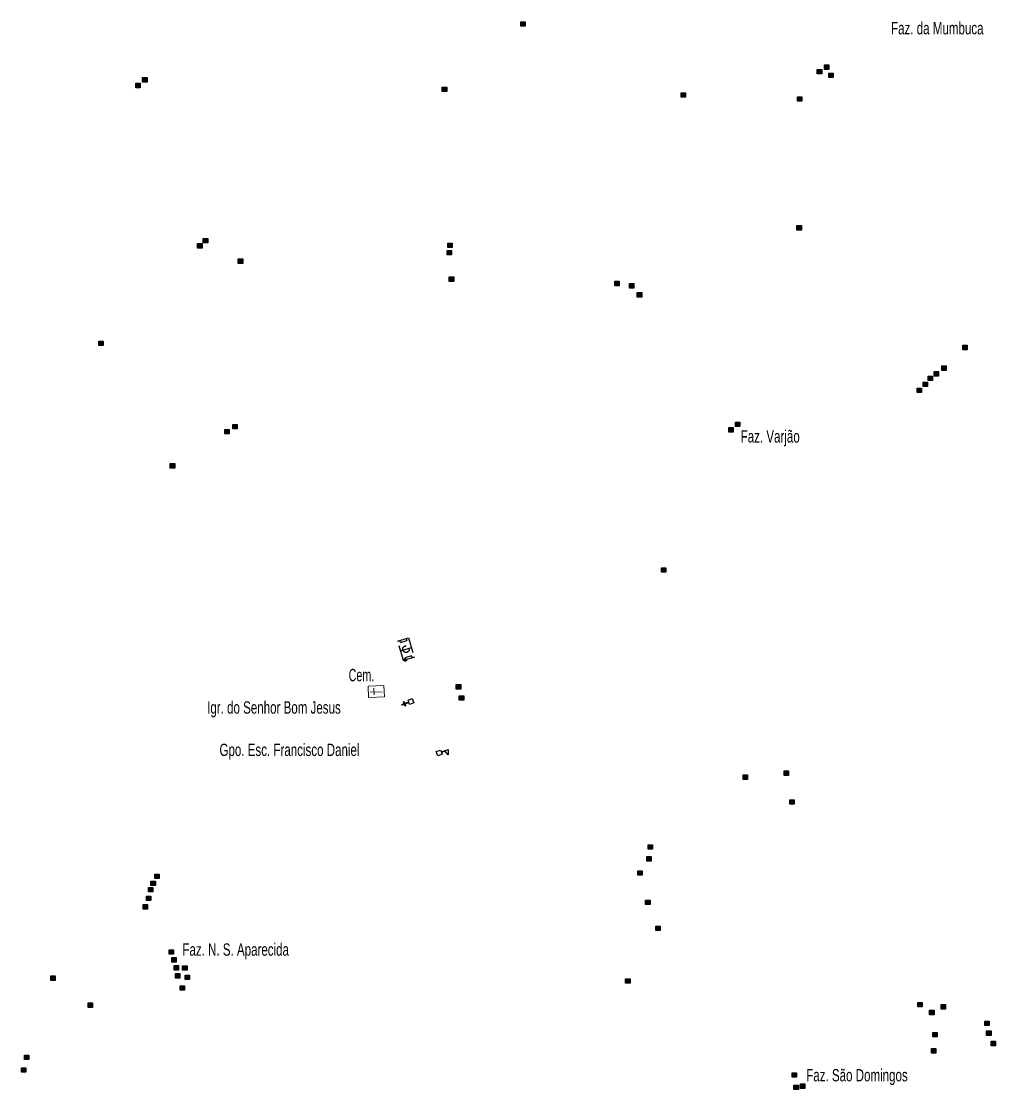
# Model space of a CAD drawing. Extents: x 265.7 to 292.1, y 7676.2 to 7704.2.
# Drawn here: x 273.12 to 279.43, y 7683.25 to 7690.17 of the extents above; entities that cross this region are included whole.
import ezdxf

# ---------------------------------------------------------------- set-up
doc = ezdxf.new("R2010")
doc.units = 0
doc.header["$LTSCALE"] = 0.032
doc.header["$PDMODE"] = 32
doc.header["$PDSIZE"] = 0.016
doc.linetypes.add('MEDIUM_DASHED', pattern=[4.5, 3, -1.5])
for name, color, linetype, lineweight in [('14', 7, 'MEDIUM_DASHED', 25), ('2', 7, 'Continuous', 25), ('21', 7, 'MEDIUM_DASHED', 13), ('4', 7, 'Continuous', 25), ('6', 7, 'Continuous', 25)]:
    doc.layers.add(name, color=color, linetype=linetype, lineweight=lineweight)
doc.layers.add('61', color=7, linetype='Continuous')

msp = doc.modelspace()

# ---------------------------------------------------------------- hatches: boundary and pattern name
at = {"layer": '2'}
for points in [[(276.3557, 7690.1714), (276.3847, 7690.1714), (276.3847, 7690.1424), (276.3557, 7690.1424)], [(278.3241, 7689.8922), (278.3531, 7689.8922), (278.3531, 7689.8632), (278.3241, 7689.8632)], [(273.9054, 7689.8099), (273.9344, 7689.8099), (273.9344, 7689.7809), (273.9054, 7689.7809)], [(278.2773, 7689.8631), (278.3063, 7689.8631), (278.3063, 7689.8341), (278.2773, 7689.8341)], [(278.3516, 7689.839), (278.3806, 7689.839), (278.3806, 7689.81), (278.3516, 7689.81)], [(273.8602, 7689.7727), (273.8892, 7689.7727), (273.8892, 7689.7437), (273.8602, 7689.7437)], [(275.8472, 7689.7485), (275.8762, 7689.7485), (275.8762, 7689.7195), (275.8472, 7689.7195)], [(277.3952, 7689.7114), (277.4242, 7689.7114), (277.4242, 7689.6824), (277.3952, 7689.6824)], [(278.149, 7689.6856), (278.178, 7689.6856), (278.178, 7689.6566), (278.149, 7689.6566)], [(278.145, 7688.8503), (278.174, 7688.8503), (278.174, 7688.8213), (278.145, 7688.8213)], [(274.2614, 7688.7333), (274.2904, 7688.7333), (274.2904, 7688.7043), (274.2614, 7688.7043)], [(274.2977, 7688.7672), (274.3267, 7688.7672), (274.3267, 7688.7382), (274.2977, 7688.7382)], [(275.8828, 7688.7373), (275.9118, 7688.7373), (275.9118, 7688.7083), (275.8828, 7688.7083)], [(274.5253, 7688.634), (274.5543, 7688.634), (274.5543, 7688.605), (274.5253, 7688.605)], [(275.8779, 7688.6888), (275.9069, 7688.6888), (275.9069, 7688.6598), (275.8779, 7688.6598)], [(275.8924, 7688.5178), (275.9214, 7688.5178), (275.9214, 7688.4888), (275.8924, 7688.4888)], [(276.965, 7688.4895), (276.994, 7688.4895), (276.994, 7688.4605), (276.965, 7688.4605)], [(277.0601, 7688.4742), (277.0891, 7688.4742), (277.0891, 7688.4452), (277.0601, 7688.4452)], [(277.1103, 7688.4154), (277.1393, 7688.4154), (277.1393, 7688.3864), (277.1103, 7688.3864)], [(273.6207, 7688.1012), (273.6497, 7688.1012), (273.6497, 7688.0722), (273.6207, 7688.0722)], [(279.2199, 7688.0747), (279.2489, 7688.0747), (279.2489, 7688.0457), (279.2199, 7688.0457)], [(279.0835, 7687.9408), (279.1125, 7687.9408), (279.1125, 7687.9118), (279.0835, 7687.9118)], [(278.9956, 7687.8746), (279.0246, 7687.8746), (279.0246, 7687.8456), (278.9956, 7687.8456)], [(279.0343, 7687.9036), (279.0633, 7687.9036), (279.0633, 7687.8746), (279.0343, 7687.8746)], [(278.9632, 7687.8358), (278.9922, 7687.8358), (278.9922, 7687.8068), (278.9632, 7687.8068)], [(278.9246, 7687.7971), (278.9536, 7687.7971), (278.9536, 7687.7681), (278.9246, 7687.7681)], [(274.4372, 7687.5291), (274.4662, 7687.5291), (274.4662, 7687.5001), (274.4372, 7687.5001)], [(274.4898, 7687.5607), (274.5188, 7687.5607), (274.5188, 7687.5317), (274.4898, 7687.5317)], [(277.7035, 7687.5405), (277.7325, 7687.5405), (277.7325, 7687.5115), (277.7035, 7687.5115)], [(277.7471, 7687.5759), (277.7761, 7687.5759), (277.7761, 7687.5469), (277.7471, 7687.5469)], [(274.0846, 7687.3072), (274.1136, 7687.3072), (274.1136, 7687.2782), (274.0846, 7687.2782)], [(277.2676, 7686.6317), (277.2966, 7686.6317), (277.2966, 7686.6027), (277.2676, 7686.6027)], [(275.9376, 7685.8746), (275.9666, 7685.8746), (275.9666, 7685.8456), (275.9376, 7685.8456)], [(275.9571, 7685.8021), (275.9861, 7685.8021), (275.9861, 7685.7731), (275.9571, 7685.7731)], [(278.0626, 7685.3146), (278.0916, 7685.3146), (278.0916, 7685.2856), (278.0626, 7685.2856)], [(277.7962, 7685.2887), (277.8252, 7685.2887), (277.8252, 7685.2597), (277.7962, 7685.2597)], [(278.099, 7685.1274), (278.128, 7685.1274), (278.128, 7685.0984), (278.099, 7685.0984)], [(277.1805, 7684.8361), (277.2095, 7684.8361), (277.2095, 7684.8071), (277.1805, 7684.8071)], [(277.1725, 7684.7594), (277.2015, 7684.7594), (277.2015, 7684.7304), (277.1725, 7684.7304)], [(273.9832, 7684.6464), (274.0122, 7684.6464), (274.0122, 7684.6174), (273.9832, 7684.6174)], [(277.1143, 7684.6673), (277.1433, 7684.6673), (277.1433, 7684.6383), (277.1143, 7684.6383)], [(273.9433, 7684.5592), (273.9723, 7684.5592), (273.9723, 7684.5302), (273.9433, 7684.5302)], [(273.9587, 7684.6004), (273.9877, 7684.6004), (273.9877, 7684.5714), (273.9587, 7684.5714)], [(273.9296, 7684.5028), (273.9586, 7684.5028), (273.9586, 7684.4738), (273.9296, 7684.4738)], [(277.1643, 7684.4769), (277.1933, 7684.4769), (277.1933, 7684.4479), (277.1643, 7684.4479)], [(273.9087, 7684.4485), (273.9377, 7684.4485), (273.9377, 7684.4195), (273.9087, 7684.4195)], [(277.2306, 7684.309), (277.2596, 7684.309), (277.2596, 7684.28), (277.2306, 7684.28)], [(274.0766, 7684.1557), (274.1056, 7684.1557), (274.1056, 7684.1267), (274.0766, 7684.1267)], [(274.0943, 7684.1049), (274.1233, 7684.1049), (274.1233, 7684.0759), (274.0943, 7684.0759)], [(274.1089, 7684.0524), (274.1379, 7684.0524), (274.1379, 7684.0234), (274.1089, 7684.0234)], [(274.1178, 7684.0007), (274.1468, 7684.0007), (274.1468, 7683.9717), (274.1178, 7683.9717)], [(274.1641, 7684.0511), (274.1931, 7684.0511), (274.1931, 7684.0221), (274.1641, 7684.0221)], [(274.1807, 7683.991), (274.2097, 7683.991), (274.2097, 7683.962), (274.1807, 7683.962)], [(273.3099, 7683.9854), (273.3389, 7683.9854), (273.3389, 7683.9564), (273.3099, 7683.9564)], [(274.1476, 7683.9216), (274.1766, 7683.9216), (274.1766, 7683.8926), (274.1476, 7683.8926)], [(277.0352, 7683.9668), (277.0642, 7683.9668), (277.0642, 7683.9378), (277.0352, 7683.9378)], [(273.5512, 7683.8103), (273.5802, 7683.8103), (273.5802, 7683.7813), (273.5512, 7683.7813)], [(278.9279, 7683.8135), (278.9569, 7683.8135), (278.9569, 7683.7845), (278.9279, 7683.7845)], [(279.0794, 7683.7998), (279.1084, 7683.7998), (279.1084, 7683.7708), (279.0794, 7683.7708)], [(279.0053, 7683.7635), (279.0343, 7683.7635), (279.0343, 7683.7345), (279.0053, 7683.7345)], [(279.3627, 7683.6925), (279.3917, 7683.6925), (279.3917, 7683.6635), (279.3627, 7683.6635)], [(279.0255, 7683.6198), (279.0545, 7683.6198), (279.0545, 7683.5908), (279.0255, 7683.5908)], [(279.3748, 7683.6295), (279.4038, 7683.6295), (279.4038, 7683.6005), (279.3748, 7683.6005)], [(279.0173, 7683.5149), (279.0463, 7683.5149), (279.0463, 7683.4859), (279.0173, 7683.4859)], [(279.404, 7683.5617), (279.433, 7683.5617), (279.433, 7683.5327), (279.404, 7683.5327)], [(273.1388, 7683.473), (273.1678, 7683.473), (273.1678, 7683.444), (273.1388, 7683.444)], [(273.1194, 7683.3906), (273.1484, 7683.3906), (273.1484, 7683.3616), (273.1194, 7683.3616)], [(278.1143, 7683.3584), (278.1433, 7683.3584), (278.1433, 7683.3294), (278.1143, 7683.3294)], [(278.1256, 7683.2775), (278.1546, 7683.2775), (278.1546, 7683.2485), (278.1256, 7683.2485)], [(278.1681, 7683.2857), (278.1971, 7683.2857), (278.1971, 7683.2567), (278.1681, 7683.2567)]]:
    msp.add_hatch(color=256, dxfattribs=at).paths.add_polyline_path(points)

# ---------------------------------------------------------------- linework, layer by layer
at = {"layer": '14'}
for p, q in [((275.5756, 7686.1468), (275.5715, 7686.1605)), ((275.5756, 7686.1468), (275.6182, 7686.1598)), ((275.614, 7686.1735), (275.6182, 7686.1598)), ((275.577, 7686.0936), (275.6469, 7686.115)), ((275.6482, 7686.0618), (275.6057, 7686.0487)), ((275.6099, 7686.0351), (275.6057, 7686.0487)), ((275.6063, 7686.0338), (275.6064, 7686.0339)), ((275.6482, 7686.0618), (275.6523, 7686.0481)), ((275.6506, 7686.0476), (275.651, 7686.0473))]:
    msp.add_line(p, q, dxfattribs=at)
msp.add_lwpolyline([(275.666, 7686.0523), (275.5962, 7686.0309), (275.5578, 7686.1563), (275.6277, 7686.1777)], close=True, dxfattribs=at)
msp.add_circle((275.6119, 7686.1043), 0.0212, dxfattribs=at)
msp.add_point((275.6066, 7686.0341), dxfattribs=at)
at = {"layer": '2'}
for points in [[(276.3557, 7690.1714), (276.3847, 7690.1714), (276.3847, 7690.1424), (276.3557, 7690.1424)], [(278.3241, 7689.8922), (278.3531, 7689.8922), (278.3531, 7689.8632), (278.3241, 7689.8632)], [(273.9054, 7689.8099), (273.9344, 7689.8099), (273.9344, 7689.7809), (273.9054, 7689.7809)], [(278.2773, 7689.8631), (278.3063, 7689.8631), (278.3063, 7689.8341), (278.2773, 7689.8341)], [(278.3516, 7689.839), (278.3806, 7689.839), (278.3806, 7689.81), (278.3516, 7689.81)], [(273.8602, 7689.7727), (273.8892, 7689.7727), (273.8892, 7689.7437), (273.8602, 7689.7437)], [(275.8472, 7689.7485), (275.8762, 7689.7485), (275.8762, 7689.7195), (275.8472, 7689.7195)], [(277.3952, 7689.7114), (277.4242, 7689.7114), (277.4242, 7689.6824), (277.3952, 7689.6824)], [(278.149, 7689.6856), (278.178, 7689.6856), (278.178, 7689.6566), (278.149, 7689.6566)], [(278.145, 7688.8503), (278.174, 7688.8503), (278.174, 7688.8213), (278.145, 7688.8213)], [(274.2614, 7688.7333), (274.2904, 7688.7333), (274.2904, 7688.7043), (274.2614, 7688.7043)], [(274.2977, 7688.7672), (274.3267, 7688.7672), (274.3267, 7688.7382), (274.2977, 7688.7382)], [(275.8828, 7688.7373), (275.9118, 7688.7373), (275.9118, 7688.7083), (275.8828, 7688.7083)], [(274.5253, 7688.634), (274.5543, 7688.634), (274.5543, 7688.605), (274.5253, 7688.605)], [(275.8779, 7688.6888), (275.9069, 7688.6888), (275.9069, 7688.6598), (275.8779, 7688.6598)], [(275.8924, 7688.5178), (275.9214, 7688.5178), (275.9214, 7688.4888), (275.8924, 7688.4888)], [(276.965, 7688.4895), (276.994, 7688.4895), (276.994, 7688.4605), (276.965, 7688.4605)], [(277.0601, 7688.4742), (277.0891, 7688.4742), (277.0891, 7688.4452), (277.0601, 7688.4452)], [(277.1103, 7688.4154), (277.1393, 7688.4154), (277.1393, 7688.3864), (277.1103, 7688.3864)], [(273.6207, 7688.1012), (273.6497, 7688.1012), (273.6497, 7688.0722), (273.6207, 7688.0722)], [(279.2199, 7688.0747), (279.2489, 7688.0747), (279.2489, 7688.0457), (279.2199, 7688.0457)], [(279.0835, 7687.9408), (279.1125, 7687.9408), (279.1125, 7687.9118), (279.0835, 7687.9118)], [(278.9956, 7687.8746), (279.0246, 7687.8746), (279.0246, 7687.8456), (278.9956, 7687.8456)], [(279.0343, 7687.9036), (279.0633, 7687.9036), (279.0633, 7687.8746), (279.0343, 7687.8746)], [(278.9632, 7687.8358), (278.9922, 7687.8358), (278.9922, 7687.8068), (278.9632, 7687.8068)], [(278.9246, 7687.7971), (278.9536, 7687.7971), (278.9536, 7687.7681), (278.9246, 7687.7681)], [(274.4372, 7687.5291), (274.4662, 7687.5291), (274.4662, 7687.5001), (274.4372, 7687.5001)], [(274.4898, 7687.5607), (274.5188, 7687.5607), (274.5188, 7687.5317), (274.4898, 7687.5317)], [(277.7035, 7687.5405), (277.7325, 7687.5405), (277.7325, 7687.5115), (277.7035, 7687.5115)], [(277.7471, 7687.5759), (277.7761, 7687.5759), (277.7761, 7687.5469), (277.7471, 7687.5469)], [(274.0846, 7687.3072), (274.1136, 7687.3072), (274.1136, 7687.2782), (274.0846, 7687.2782)], [(277.2676, 7686.6317), (277.2966, 7686.6317), (277.2966, 7686.6027), (277.2676, 7686.6027)], [(275.9376, 7685.8746), (275.9666, 7685.8746), (275.9666, 7685.8456), (275.9376, 7685.8456)], [(275.9571, 7685.8021), (275.9861, 7685.8021), (275.9861, 7685.7731), (275.9571, 7685.7731)], [(278.0626, 7685.3146), (278.0916, 7685.3146), (278.0916, 7685.2856), (278.0626, 7685.2856)], [(277.7962, 7685.2887), (277.8252, 7685.2887), (277.8252, 7685.2597), (277.7962, 7685.2597)], [(278.099, 7685.1274), (278.128, 7685.1274), (278.128, 7685.0984), (278.099, 7685.0984)], [(277.1805, 7684.8361), (277.2095, 7684.8361), (277.2095, 7684.8071), (277.1805, 7684.8071)], [(277.1725, 7684.7594), (277.2015, 7684.7594), (277.2015, 7684.7304), (277.1725, 7684.7304)], [(273.9832, 7684.6464), (274.0122, 7684.6464), (274.0122, 7684.6174), (273.9832, 7684.6174)], [(277.1143, 7684.6673), (277.1433, 7684.6673), (277.1433, 7684.6383), (277.1143, 7684.6383)], [(273.9433, 7684.5592), (273.9723, 7684.5592), (273.9723, 7684.5302), (273.9433, 7684.5302)], [(273.9587, 7684.6004), (273.9877, 7684.6004), (273.9877, 7684.5714), (273.9587, 7684.5714)], [(273.9296, 7684.5028), (273.9586, 7684.5028), (273.9586, 7684.4738), (273.9296, 7684.4738)], [(277.1643, 7684.4769), (277.1933, 7684.4769), (277.1933, 7684.4479), (277.1643, 7684.4479)], [(273.9087, 7684.4485), (273.9377, 7684.4485), (273.9377, 7684.4195), (273.9087, 7684.4195)], [(277.2306, 7684.309), (277.2596, 7684.309), (277.2596, 7684.28), (277.2306, 7684.28)], [(274.0766, 7684.1557), (274.1056, 7684.1557), (274.1056, 7684.1267), (274.0766, 7684.1267)], [(274.0943, 7684.1049), (274.1233, 7684.1049), (274.1233, 7684.0759), (274.0943, 7684.0759)], [(274.1089, 7684.0524), (274.1379, 7684.0524), (274.1379, 7684.0234), (274.1089, 7684.0234)], [(274.1178, 7684.0007), (274.1468, 7684.0007), (274.1468, 7683.9717), (274.1178, 7683.9717)], [(274.1641, 7684.0511), (274.1931, 7684.0511), (274.1931, 7684.0221), (274.1641, 7684.0221)], [(274.1807, 7683.991), (274.2097, 7683.991), (274.2097, 7683.962), (274.1807, 7683.962)], [(273.3099, 7683.9854), (273.3389, 7683.9854), (273.3389, 7683.9564), (273.3099, 7683.9564)], [(274.1476, 7683.9216), (274.1766, 7683.9216), (274.1766, 7683.8926), (274.1476, 7683.8926)], [(277.0352, 7683.9668), (277.0642, 7683.9668), (277.0642, 7683.9378), (277.0352, 7683.9378)], [(273.5512, 7683.8103), (273.5802, 7683.8103), (273.5802, 7683.7813), (273.5512, 7683.7813)], [(278.9279, 7683.8135), (278.9569, 7683.8135), (278.9569, 7683.7845), (278.9279, 7683.7845)], [(279.0794, 7683.7998), (279.1084, 7683.7998), (279.1084, 7683.7708), (279.0794, 7683.7708)], [(279.0053, 7683.7635), (279.0343, 7683.7635), (279.0343, 7683.7345), (279.0053, 7683.7345)], [(279.3627, 7683.6925), (279.3917, 7683.6925), (279.3917, 7683.6635), (279.3627, 7683.6635)], [(279.0255, 7683.6198), (279.0545, 7683.6198), (279.0545, 7683.5908), (279.0255, 7683.5908)], [(279.3748, 7683.6295), (279.4038, 7683.6295), (279.4038, 7683.6005), (279.3748, 7683.6005)], [(279.0173, 7683.5149), (279.0463, 7683.5149), (279.0463, 7683.4859), (279.0173, 7683.4859)], [(279.404, 7683.5617), (279.433, 7683.5617), (279.433, 7683.5327), (279.404, 7683.5327)], [(273.1388, 7683.473), (273.1678, 7683.473), (273.1678, 7683.444), (273.1388, 7683.444)], [(273.1194, 7683.3906), (273.1484, 7683.3906), (273.1484, 7683.3616), (273.1194, 7683.3616)], [(278.1143, 7683.3584), (278.1433, 7683.3584), (278.1433, 7683.3294), (278.1143, 7683.3294)], [(278.1256, 7683.2775), (278.1546, 7683.2775), (278.1546, 7683.2485), (278.1256, 7683.2485)], [(278.1681, 7683.2857), (278.1971, 7683.2857), (278.1971, 7683.2567), (278.1681, 7683.2567)]]:
    msp.add_lwpolyline(points, close=True, dxfattribs=at)
at = {"layer": '21'}
for p, q in [((275.3803, 7685.8266), (275.4579, 7685.826)), ((275.4043, 7685.8513), (275.4066, 7685.8072))]:
    msp.add_line(p, q, dxfattribs=at)
msp.add_lwpolyline([(275.3658, 7685.8647), (275.4691, 7685.8682), (275.4716, 7685.795), (275.3684, 7685.7914)], close=True, dxfattribs=at)
at = {"layer": '4'}
for points in [[(275.8414, 7685.4341), (275.8454, 7685.4227), (275.818, 7685.4132), (275.8084, 7685.4406), (275.8358, 7685.4501), (275.8398, 7685.4388)], [(275.8398, 7685.4388), (275.8855, 7685.4547), (275.8857, 7685.4188), (275.866, 7685.4427), (275.8414, 7685.4341)]]:
    msp.add_lwpolyline(points, dxfattribs=at)
at = {"layer": '6'}
for points in [[(275.631, 7685.7577), (275.6056, 7685.7484), (275.6097, 7685.737), (275.6051, 7685.7353), (275.6009, 7685.7467), (275.5856, 7685.741), (275.5839, 7685.7456), (275.5993, 7685.7512), (275.5952, 7685.7626), (275.5998, 7685.7642), (275.6039, 7685.7529), (275.6294, 7685.7622)], [(275.6294, 7685.7622), (275.6252, 7685.7736), (275.6524, 7685.7835), (275.6624, 7685.7564), (275.6352, 7685.7463), (275.631, 7685.7577)]]:
    msp.add_lwpolyline(points, dxfattribs=at)

# ---------------------------------------------------------------- texts
at = {"layer": '61'}
for s, width, p in [('Faz. da Mumbuca', 0.7, (278.7553, 7690.09)), ('Faz. Varjão', 0.7, (277.7808, 7687.4437)), ('Cem.', 0.65, (275.2401, 7685.8961)), ('Igr. do Senhor Bom Jesus', 0.7, (274.3234, 7685.686)), ('Gpo. Esc. Francisco Daniel', 0.7, (274.4032, 7685.4114)), ('Faz. N. S. Aparecida', 0.7, (274.1628, 7684.1167)), ('Faz. São Domingos', 0.7, (278.2056, 7683.3021))]:
    msp.add_text(s, height=0.08, dxfattribs=dict(at, width=width)).set_placement(p)

doc.saveas('drawing.dxf')
